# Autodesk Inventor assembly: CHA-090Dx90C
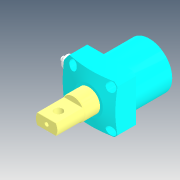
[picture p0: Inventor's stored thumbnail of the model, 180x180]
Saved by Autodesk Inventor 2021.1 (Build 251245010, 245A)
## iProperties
Created: 2018-07
Part Number: CHA-090Dx90C
Description: STEP AP214
Document SubType Name: Assembly
Designer: user
Title: CHA-090Dx90C.STEP
Revision Number: ÈÎºÎ
Sending System: SolidWorks 2016
Preprocessor: SwSTEP 2.0
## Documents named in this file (5)
- D:\Vault_2016\Projekty\Clamptek\Hydraulic\CHA\CHA\CHA-090\Inventor\CHA-090Dx90C\CHA-090Dx90C.iam
- D:\Vault_2016\Projekty\Clamptek\Hydraulic\CHA\CHA\CHA-090\Inventor\CHA-090Dx90C\CHA-090C±¾Ìå.ipt
- D:\Vault_2016\Projekty\Clamptek\Hydraulic\CHA\CHA\CHA-090\Inventor\CHA-090Dx90C\CHA-090D»îÈû¸Ë.ipt
- D:\Vault_2016\Projekty\Clamptek\Hydraulic\CHA\CHA\CHA-090\Inventor\CHA-090Dx90C\G3-8¶ÂÍ·.ipt
- D:\Vault_2016\Projekty\Clamptek\Hydraulic\CHA\CHA\CHA-090\Inventor\CHA-090Dx90C\CZL30µ÷ËÙ·§.iam
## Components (4 placed, 4 different names)
1. CHA-090C±¾Ìå_1
2. CHA-090D»îÈû¸Ë_2
3. G3-8¶ÂÍ·_3
4. CZL30µ÷ËÙ·§_4 [sub-assembly]
